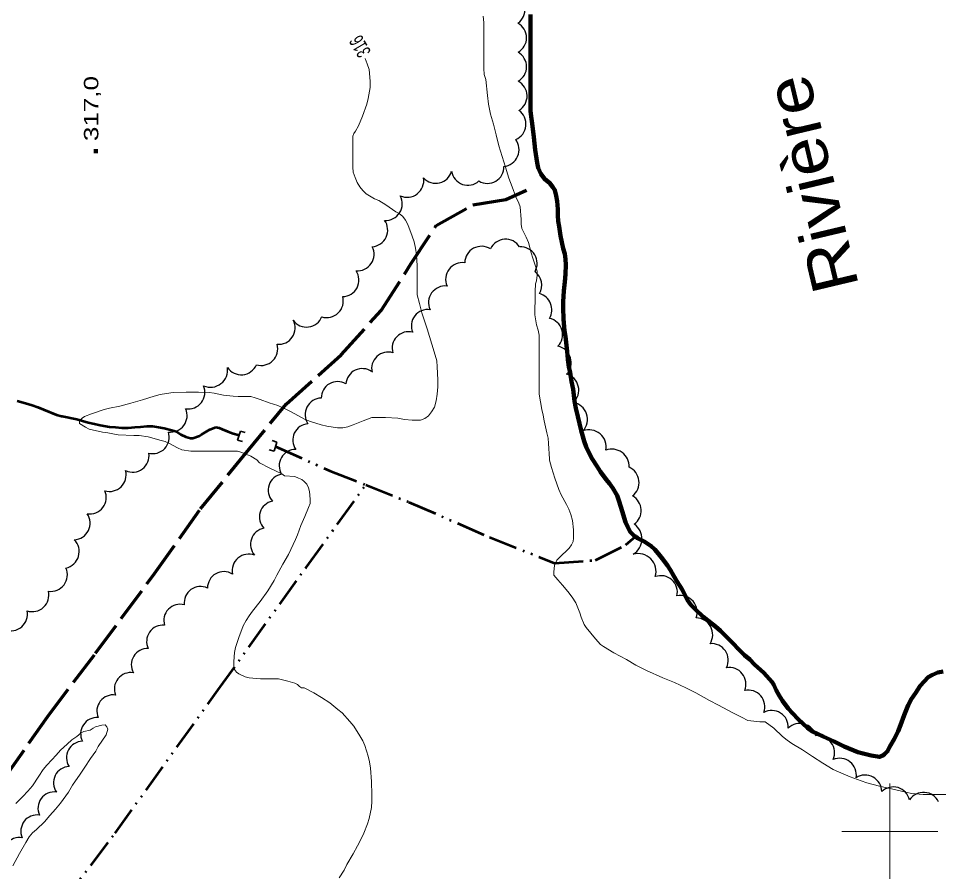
# Model space of a CAD drawing. Extents: x 240591 to 242335, y 5323482 to 5326937.
# Drawn here: x 242018.5 to 242210.1, y 5325991.6 to 5326169.4 of the extents above; entities that cross this region are included whole.
import ezdxf

# ---------------------------------------------------------------- set-up
doc = ezdxf.new("R2010")
doc.units = 0
doc.header["$LTSCALE"] = 1.2
doc.linetypes.add('DASH_DOUBLE_DOT', pattern=[9.2, 5, -1.2, 0.3, -1.2, 0.3, -1.2])
doc.linetypes.add('LONG_DASHED', pattern=[7.5, 6, -1.5])
for name, color, linetype, lineweight in [('2', 7, 'Continuous', 13), ('22', 7, 'LONG_DASHED', 70), ('26', 7, 'Continuous', 35), ('3', 7, 'Continuous', 140), ('4', 7, 'DASH_DOUBLE_DOT', 53), ('44', 7, 'Continuous', 25), ('61', 7, 'Continuous', 13)]:
    doc.layers.add(name, color=color, linetype=linetype, lineweight=lineweight)

msp = doc.modelspace()

# ---------------------------------------------------------------- linework, layer by layer
at = {"layer": '2'}
for points in [[(242126.5, 5326116.7), (242125.6, 5326119.4), (242125.3, 5326120.5), (242124.7, 5326122.7), (242124.2, 5326123.8), (242123.3, 5326125.6), (242123.2, 5326126.5), (242123.2, 5326127.5), (242123, 5326130.1), (242122.7, 5326130.9), (242122.1, 5326132.2), (242121.3, 5326134.3), (242120.6, 5326136.1), (242119.9, 5326138.4), (242119.2, 5326140.6), (242118.5, 5326142.8), (242118, 5326145.1), (242117.4, 5326147.3), (242116.8, 5326149.4), (242116.4, 5326151.5), (242116.2, 5326153.3), (242115.8, 5326156.6), (242115.5, 5326157.7), (242115.4, 5326158.9), (242115.4, 5326160.2), (242115.4, 5326162.9), (242115.4, 5326165.7), (242115.4, 5326168.5), (242115.3, 5326169.8)], [(242095, 5326130.5), (242093.5, 5326131.4), (242092.6, 5326131.8), (242090.9, 5326132.8), (242090.2, 5326133.5), (242089.6, 5326134.3), (242089, 5326135.2), (242088.6, 5326136.2), (242088.2, 5326137.3), (242088.1, 5326138.4), (242088.1, 5326139.4), (242088.1, 5326142.1), (242088.1, 5326144.8), (242088.3, 5326145.4), (242088.7, 5326145.9), (242089.3, 5326147), (242090.1, 5326149), (242091, 5326151.5), (242091.3, 5326152.7), (242091.7, 5326155), (242091.7, 5326156.3), (242091.5, 5326158.7), (242091.1, 5326159.9), (242090.7, 5326161)], [(242076, 5326073.9), (242073.9, 5326074.1), (242073.3, 5326074.5), (242070.8, 5326075.7), (242068.7, 5326076.8), (242068.1, 5326077.4), (242066.9, 5326078.2), (242066.4, 5326078.4), (242064.8, 5326079), (242064.1, 5326079.2), (242063.4, 5326079.2), (242060.3, 5326079.2), (242057.1, 5326079.2), (242054.4, 5326079.2), (242052.5, 5326079.5), (242051.6, 5326079.9), (242049.9, 5326080.8), (242049, 5326081.2), (242048.2, 5326081.4), (242045.5, 5326082.2), (242043.6, 5326082.5), (242042.5, 5326082.5), (242039.2, 5326082.6), (242038.1, 5326082.8), (242037.1, 5326083), (242036, 5326083.2), (242033.2, 5326083.8), (242032.4, 5326084.2), (242031.2, 5326085), (242031.2, 5326085.6), (242031.7, 5326086.1), (242032.2, 5326086.4), (242033.7, 5326087), (242036.3, 5326087.9), (242037.4, 5326088.2), (242039.6, 5326088.6), (242041.9, 5326089.2), (242044.3, 5326089.9), (242046.7, 5326090.7), (242048, 5326091), (242049.3, 5326091.2), (242050.7, 5326091.4), (242053.4, 5326091.5), (242056, 5326091.5), (242058.2, 5326091.4), (242059.2, 5326091.3), (242061.2, 5326090.9), (242063.2, 5326090.7), (242064.2, 5326090.6), (242066.9, 5326090.6), (242067.8, 5326090.3), (242068.8, 5326090), (242070.7, 5326089.3), (242072.5, 5326088.7), (242074.3, 5326087.9), (242075.3, 5326087.4), (242078.2, 5326085.8), (242079.3, 5326085.4), (242081.5, 5326084.7), (242082.7, 5326084.4), (242084.9, 5326084.1), (242086, 5326084.1), (242087.1, 5326084.3), (242088.2, 5326084.7), (242090.3, 5326085.5), (242092.1, 5326086.2), (242092.9, 5326086.2), (242094.9, 5326086.2), (242097.5, 5326086.1), (242098.9, 5326085.8), (242100.5, 5326085.7), (242102.2, 5326085.7), (242103.1, 5326086), (242103.9, 5326086.6), (242104.5, 5326087.4), (242105.1, 5326088.4), (242105.5, 5326089.7), (242105.7, 5326091.1), (242105.8, 5326092.6), (242105.8, 5326094.1), (242105.7, 5326096.8), (242105.6, 5326098), (242105.3, 5326099.2), (242104.6, 5326101.5), (242103.6, 5326104.7), (242102.5, 5326108), (242102, 5326110), (242101.5, 5326111.8), (242101.5, 5326112.8), (242101.5, 5326114.8), (242101.5, 5326117.8), (242101.4, 5326120.1), (242101.2, 5326121.5), (242100.9, 5326122.8), (242100.5, 5326124), (242099.6, 5326126.4), (242099.1, 5326127.3), (242098.5, 5326128.1), (242097.8, 5326128.7), (242097.1, 5326129.1), (242095, 5326130.5)], [(242172.9, 5326022.8), (242170.4, 5326023.1), (242169.1, 5326023.8), (242167.3, 5326024.7), (242164.3, 5326026.3), (242162.4, 5326027.3), (242159.6, 5326028.9), (242157.5, 5326029.9), (242155.1, 5326031), (242152.7, 5326032), (242149.3, 5326033.5), (242147.1, 5326034.6), (242145.1, 5326035.8), (242142.5, 5326037.2), (242140.3, 5326038.5), (242139.7, 5326038.9), (242138.7, 5326040.1), (242136.7, 5326042.5), (242136.3, 5326043.1), (242135.7, 5326044.6), (242135.4, 5326045.5), (242134.6, 5326047.6), (242133.8, 5326048.8), (242132.9, 5326050), (242131.8, 5326051.3), (242130.8, 5326052.4), (242130, 5326053.4), (242130, 5326054.1), (242130.1, 5326055.4), (242130.6, 5326056.5), (242131.1, 5326057), (242133.2, 5326059), (242133.7, 5326059.7), (242134, 5326060.4), (242134.1, 5326061.1), (242134.1, 5326062.8), (242133.9, 5326064.8), (242133.5, 5326066), (242133.1, 5326067.1), (242132.6, 5326068.1), (242131.5, 5326070.1), (242131, 5326071.2), (242130.2, 5326073.6), (242129.5, 5326075.8), (242129.1, 5326077.3), (242129.1, 5326077.6)], [(242212.2, 5326007.7), (242209.5, 5326007.7), (242206.9, 5326007.7), (242204.5, 5326007.9), (242203.3, 5326008.2), (242200.6, 5326008.8), (242197.8, 5326009.4), (242195.2, 5326010.1), (242194, 5326010.5), (242191.7, 5326011.4), (242189.3, 5326012.4), (242188.2, 5326012.9), (242186, 5326014.2), (242183.9, 5326015.6), (242181.8, 5326017), (242179.6, 5326018.3), (242178.6, 5326019), (242177.6, 5326019.8), (242175.8, 5326021.5), (242174, 5326022.8), (242173.4, 5326022.8), (242172.9, 5326022.8)], [(242033.4, 5326021.1), (242032.1, 5326020.8), (242031.5, 5326020.5), (242030.6, 5326019.8), (242029.6, 5326019.1), (242028.6, 5326018.2), (242027.2, 5326016.9), (242026.3, 5326015.9), (242025.4, 5326014.9), (242024.4, 5326013.8), (242023.6, 5326012.9), (242022.7, 5326011.5), (242021.4, 5326009.5), (242020.4, 5326008.4), (242019.4, 5326007.3), (242017.9, 5326005.8)]]:
    msp.add_lwpolyline(points, dxfattribs=at)
at = {"layer": '2', "linetype": 'LONG_DASHED'}
for points in [[(242129.1, 5326077.6), (242128.9, 5326080.8), (242128.8, 5326081.9), (242128.5, 5326083), (242128, 5326085.5), (242127.8, 5326086.7), (242127.5, 5326087.9), (242126.9, 5326091.1), (242126.9, 5326092.2), (242126.9, 5326095.8), (242126.9, 5326099.3), (242126.9, 5326102.4), (242126.9, 5326103.4), (242126.7, 5326104.4), (242126.4, 5326105.5), (242126, 5326107.6), (242126, 5326108.7), (242126.1, 5326110.7), (242126.1, 5326112.5), (242126.2, 5326114.1), (242126.4, 5326114.7), (242126.5, 5326115.9), (242126.5, 5326116.7)], [(242068.8, 5326047.9), (242070.4, 5326050.1), (242071.7, 5326052.3), (242072.3, 5326053.4), (242073.5, 5326055.7), (242074.7, 5326057.7), (242076.2, 5326060.8), (242076.6, 5326061.8), (242077.3, 5326063.7), (242078.1, 5326065.6), (242078.9, 5326067.5), (242079.2, 5326068.3), (242079.2, 5326069.2), (242079.1, 5326070.8), (242078.9, 5326071.6), (242078.5, 5326072.3), (242078, 5326072.9), (242077.5, 5326073.3), (242076.8, 5326073.6), (242076, 5326073.9)], [(242085.3, 5325990.3), (242086.3, 5325991.9), (242086.9, 5325993.1), (242088.2, 5325995.3), (242089.1, 5325997), (242090, 5325998.7), (242090.4, 5325999.6), (242091.2, 5326001.6), (242091.5, 5326002.7), (242092, 5326005), (242092.1, 5326006.3), (242092.1, 5326007.6), (242092, 5326010.4), (242091.8, 5326013.2), (242091.6, 5326014.5), (242091.3, 5326015.7), (242090.6, 5326017.9), (242090.2, 5326018.9), (242089.6, 5326019.9), (242088.3, 5326021.9), (242087.5, 5326022.9), (242085.9, 5326024.7), (242085, 5326025.4), (242083.3, 5326026.8), (242081.6, 5326027.9), (242080, 5326028.9), (242078, 5326029.9), (242077.4, 5326029.9), (242077, 5326030.2), (242076.6, 5326030.6), (242076, 5326030.9), (242074.6, 5326031.3), (242072.6, 5326031.8), (242071.7, 5326031.8), (242068.9, 5326031.8), (242066.5, 5326032), (242065.7, 5326032.2), (242064.4, 5326032.8), (242063.9, 5326033.2), (242063.5, 5326033.7), (242063.3, 5326034.5), (242063.3, 5326035.4), (242063.5, 5326037.3), (242063.7, 5326038.3), (242064.4, 5326040.4), (242065.3, 5326042.8), (242065.9, 5326043.9), (242066.5, 5326044.9), (242067.2, 5326045.9), (242068.8, 5326047.9)], [(242017.3, 5325992.8), (242018.7, 5325995.4), (242020, 5325997.7), (242020.7, 5325998.9), (242021.4, 5325999.7), (242022.2, 5326000.4), (242023.9, 5326002), (242025, 5326003.3), (242026.2, 5326004.6), (242027.2, 5326005.9), (242028.9, 5326008.2), (242029.7, 5326009.6), (242031.3, 5326011.9), (242032.3, 5326013.4), (242033.5, 5326015.2), (242034.6, 5326016.7), (242035.1, 5326017.7), (242036.7, 5326020.1), (242037.1, 5326021.3), (242036.9, 5326021.8), (242036.5, 5326022.2), (242035.8, 5326022.1), (242034.5, 5326021.8), (242034, 5326021.5), (242033.4, 5326021.1)]]:
    msp.add_lwpolyline(points, dxfattribs=at)
at = {"layer": '22'}
msp.add_lwpolyline([(241919.1, 5325890.8), (241928.3, 5325895.4), (241938.3, 5325902.7), (241946.8, 5325913.1), (241955.9, 5325924.8), (241965.6, 5325938.6), (241977, 5325954.3), (241986.1, 5325969.1), (241995.2, 5325983.1), (242004.1, 5325995.5), (242015.5, 5326011), (242024.5, 5326023.9), (242034.5, 5326037.1), (242046.8, 5326053.7), (242056.4, 5326067.2), (242065.2, 5326078), (242074.2, 5326089), (242085.7, 5326099.3), (242094, 5326108.5), (242100.2, 5326118.2), (242105.5, 5326126.2), (242113.1, 5326130.5), (242120, 5326131.6), (242124.3, 5326133.6)], dxfattribs=at)
at = {"layer": '26'}
for p, q in [((242064.1, 5326081.5), (242064.7, 5326083.4)), ((242064.7, 5326083.4), (242065.7, 5326083.1)), ((242064.1, 5326081.5), (242065.1, 5326081.2)), ((242072.3, 5326081.1), (242071.3, 5326081.4)), ((242071.7, 5326079.2), (242070.7, 5326079.5)), ((242072.3, 5326081.1), (242071.7, 5326079.2))]:
    msp.add_line(p, q, dxfattribs=at)
at = {"layer": '3'}
msp.add_line((242034.6, 5326141.3), (242034.6, 5326142.1), dxfattribs=at)
at = {"layer": '4', "linetype": 'Continuous', "lineweight": 90}
for points in [[(242125.1, 5326170.2), (242125.1, 5326167.5), (242125.1, 5326164.7), (242125.1, 5326161.5), (242125.1, 5326158.7), (242125.1, 5326155.5), (242125.1, 5326152.7), (242125.1, 5326150.1), (242125.3, 5326148.9), (242125.5, 5326147.5), (242125.8, 5326144.6), (242126.1, 5326142), (242126.5, 5326139.3), (242126.7, 5326138.2), (242127.3, 5326137), (242128.1, 5326135.9), (242129.1, 5326135.1), (242129.8, 5326134.2), (242130.2, 5326133.6), (242130.5, 5326132.4), (242130.7, 5326131.3), (242130.8, 5326129.6), (242130.8, 5326128.3), (242130.9, 5326127.1), (242131.1, 5326126), (242131.4, 5326124.1), (242131.9, 5326121.4), (242132.3, 5326120.3), (242132.4, 5326119.2), (242132.5, 5326118), (242132.4, 5326116.1), (242132.3, 5326114.5), (242132.1, 5326112.6), (242131.9, 5326110.3), (242131.9, 5326109.1), (242132, 5326106.7), (242132.2, 5326104.3), (242132.4, 5326103.1), (242132.8, 5326100), (242132.9, 5326098.3), (242133.1, 5326096.8), (242133.4, 5326095.6), (242133.7, 5326093.7), (242134, 5326092.1), (242134.3, 5326089.6), (242134.6, 5326088.2), (242135, 5326086.4), (242135.7, 5326083.5), (242136.3, 5326081.3), (242136.7, 5326080.1), (242137.2, 5326079.1), (242138, 5326077.6), (242139, 5326076), (242139.7, 5326074.9), (242140.9, 5326073.3), (242141.6, 5326072.5), (242142.3, 5326071.5), (242143.2, 5326070), (242143.6, 5326068.7), (242144.2, 5326066.7), (242144.9, 5326064.4), (242145.4, 5326063.4), (242145.9, 5326062.4), (242146.8, 5326061.5), (242147, 5326061.4)], [(242147, 5326061.4), (242147.4, 5326061.1), (242148.8, 5326060.4), (242150.2, 5326059.5), (242151, 5326058.7), (242151.8, 5326057.8), (242152.6, 5326056.8), (242153.7, 5326055.4), (242154.3, 5326054.4), (242154.9, 5326053.3), (242155.6, 5326052.1), (242156.7, 5326050.4), (242157.3, 5326049.3), (242157.8, 5326048.2), (242158.5, 5326047.2), (242159.4, 5326046.3), (242161.1, 5326044.7)], [(242161.1, 5326044.7), (242162.1, 5326043.9), (242163.7, 5326042.7), (242164.7, 5326041.8), (242165.6, 5326040.9), (242167.4, 5326039.1), (242168.3, 5326038.1), (242169.7, 5326036.7), (242170.8, 5326035.8), (242171.8, 5326034.8), (242173.7, 5326033), (242175.5, 5326031.1), (242175.8, 5326030.5), (242176.3, 5326029.4), (242176.9, 5326028.3), (242177.6, 5326027.2), (242178.8, 5326025.6), (242179.7, 5326024.6), (242180.9, 5326023.4), (242182.8, 5326021.6), (242183.9, 5326020.8), (242184.9, 5326020.3), (242186.1, 5326019.8), (242188.4, 5326018.7), (242190.5, 5326017.7), (242193.3, 5326016.5), (242194.4, 5326016.2), (242196.1, 5326015.8), (242197.8, 5326015.5), (242198.5, 5326015.8), (242198.9, 5326016.1), (242199.5, 5326016.7), (242200, 5326017.7), (242200.9, 5326019.2), (242201.7, 5326020.9), (242202.2, 5326022.1), (242203, 5326024.2), (242203.8, 5326026.3), (242204.5, 5326027.6), (242205.3, 5326028.8), (242206.3, 5326030.3), (242207.1, 5326031.2), (242208, 5326032.1), (242208.9, 5326032.6), (242210, 5326033.1), (242211.1, 5326033.3)]]:
    msp.add_lwpolyline(points, dxfattribs=at)
at = {"layer": '4'}
for points in [[(242018.2, 5326089.7), (242019.9, 5326089.2), (242021.3, 5326088.8), (242022.5, 5326088.4), (242023.7, 5326087.9), (242026.4, 5326086.8), (242027.4, 5326086.5), (242027.6, 5326086.5)], [(242027.6, 5326086.5), (242030.6, 5326085.9), (242031.8, 5326085.5), (242033, 5326085.2), (242034.3, 5326084.9), (242035.5, 5326084.6), (242037.4, 5326084.3), (242038.7, 5326084.2), (242040, 5326084.1), (242041.3, 5326084.1), (242042.7, 5326084.2), (242043.9, 5326084.3), (242045.2, 5326084.4), (242046.4, 5326084.4), (242047.6, 5326084.2), (242048.8, 5326084), (242050.4, 5326083.6), (242051.4, 5326083.3), (242052.3, 5326082.7), (242053.3, 5326082.2), (242054.3, 5326081.9), (242054.8, 5326081.9), (242056.2, 5326082.4), (242056.6, 5326082.7), (242058.3, 5326083.7), (242059.6, 5326084.2), (242060.3, 5326084.1), (242060.9, 5326083.8), (242062.1, 5326083.3), (242063.2, 5326082.9), (242064.2, 5326082.6), (242064.4, 5326082.4)], [(242072, 5326080.2), (242083.3, 5326075.1), (242090.8, 5326072.2)], [(241937, 5325854.4), (241947.3, 5325869.3), (241968.4, 5325901), (241993.4, 5325936), (242013.5, 5325966.5), (242038.6, 5325999.6), (242060, 5326029.4), (242078.4, 5326055), (242090.8, 5326072.2)], [(242090.8, 5326072.2), (242099.8, 5326068.6), (242116.6, 5326061.3), (242130.1, 5326055.9), (242138.7, 5326056.5), (242145, 5326059.7), (242147, 5326061.4)]]:
    msp.add_lwpolyline(points, dxfattribs=at)
at = {"layer": '44'}
for centre, radius, start, end in [((242126.078, 5326108.657), 3.494, 329.23586, 74.74436), ((242078.47, 5326108.498), 3.437, 215.75328, 339.06054), ((242128.346, 5326103.472), 3.477, 316.07852, 77.80789), ((242130.123, 5326097.655), 3.482, 316.30696, 77.94007), ((242064.865, 5326098.559), 3.437, 213.53655, 337.07502), ((242131.714, 5326091.902), 3.473, 312.70502, 74.5434), ((242133.429, 5326085.84), 3.568, 317.50929, 79.65071), ((242137.328, 5326080.095), 3.568, 348.67646, 110.81789), ((242142.095, 5326076.059), 3.568, 357.07916, 110.81789), ((242144.189, 5326072.646), 3.549, 308.53123, 65.55111), ((242144.722, 5326066.835), 3.468, 305.67875, 61.06311), ((242027.598, 5326058.291), 3.515, 282.52623, 44.61059), ((242025.197, 5326053.463), 3.458, 261.74549, 23.83309), ((242152.259, 5326049.806), 3.466, 347.23305, 109.18591), ((242021.352, 5326049.222), 3.446, 251.70155, 13.72797), ((242156.378, 5326045.636), 3.483, 340.44288, 102.23006), ((242016.863, 5326045.256), 3.477, 249.94182, 11.50649), ((242159.596, 5326040.984), 3.486, 327.2884, 88.9562), ((242029.163, 5326010.124), 3.4, 92.75222, 214.46283), ((242194.827, 5326008.249), 3.483, 0.66807, 122.41158), ((242200.713, 5326005.823), 3.444, 12.1818, 134.2558), ((242206.996, 5326004.666), 3.472, 25.12546, 147.13344), ((242022.349, 5326000.042), 3.394, 81.67502, 203.65859), ((242018.642, 5325995.343), 3.39, 79.83528, 202.06127)]:
    msp.add_arc(centre, radius, start, end, dxfattribs=at)
for centre, major_axis, ratio, start_param, end_param in [((242120.497, 5326171.188), (3.464, 0.072), 0.999503, 5.3118832, 7.4351143), ((242120.846, 5326165.332), (3.287, -1.096), 0.999962, 5.5451523, 7.6745969), ((242120.859, 5326159.29), (3.459, -0.139), 0.998126, 5.259769, 7.3868814), ((242120.945, 5326153.182), (3.471, -0.203), 0.999507, 5.3100113, 7.4357449), ((242120.701, 5326147.363), (3.426, -0.66), 0.999402, 5.3025735, 7.4239328), ((242119.183, 5326142.052), (3.172, -1.628), 0.998415, 5.3038801, 7.3882084), ((242105.398, 5326138.455), (0.58, -3.388), 0.998982, 5.2858519, 7.4062367), ((242112.088, 5326138.038), (-0.441, -3.413), 0.996141, 4.9944276, 7.1484397), ((242116.167, 5326138.431), (2.958, 1.749), 0.999862, 3.634958, 5.7775195), ((242099.397, 5326135.612), (2.147, -2.779), 0.999995, 5.216182, 7.3442143), ((242094.95, 5326130.74), (2.919, -1.872), 0.999995, 5.2189424, 7.3492351), ((242091.913, 5326125.258), (3.149, -1.462), 0.998035, 5.2174857, 7.3413749), ((242119.951, 5326119.874), (-2.861, -1.979), 0.999995, 3.1139807, 5.2451855), ((242089.072, 5326120.225), (2.796, -2.057), 0.99833, 5.264408, 7.3895869), ((242114.908, 5326118.409), (-1.802, -2.976), 0.999995, 3.1139807, 5.2451855), ((242123.036, 5326118.301), (-3.077, 1.623), 0.999995, 3.1139807, 5.2451855), ((242110.931, 5326115.007), (-0.404, -3.455), 0.999995, 3.1139805, 5.2451854), ((242085.958, 5326114.841), (-1.711, 2.976), 0.998151, 2.6313411, 4.7882732), ((242123.933, 5326113.782), (2.205, 2.757), 0.999995, 4.8670386, 6.3088325), ((242107.361, 5326110.15), (-2.834, 2.016), 0.997831, 5.2174671, 7.34271), ((242082.68, 5326110.481), (2.475, 2.401), 0.999615, 3.6390707, 5.7857072), ((242103.707, 5326105.314), (-2.437, 2.365), 0.999677, 5.3309729, 7.4608527), ((242072.656, 5326104.882), (3.308, -0.915), 0.995576, 4.8860876, 7.0440213), ((242099.707, 5326100.682), (-2.447, 2.369), 0.999724, 5.2192385, 7.3481275), ((242069.039, 5326100.502), (3.035, 1.606), 0.99974, 3.9277517, 6.0854885), ((242095.311, 5326096.538), (-1.994, -2.706), 0.964048, 3.4397845, 5.6020965), ((242058.438, 5326096.122), (2.201, -2.853), 0.999818, 5.2215684, 7.3470084), ((242090.002, 5326093.093), (-2.578, -2.164), 0.972636, 3.3759738, 5.5356812), ((242053.83, 5326091.461), (2.732, -2.129), 0.999978, 5.2179598, 7.3451661), ((242084.928, 5326090.298), (-1.486, 3.059), 0.999109, 5.2889931, 7.4103952), ((242081.644, 5326086.812), (0.188, -3.455), 0.999995, 3.120336, 5.2435114), ((242050.127, 5326086.634), (2.799, -2.055), 0.995718, 5.2173706, 7.336718), ((242046.435, 5326082.13), (1.493, -3.095), 0.996832, 5.5690192, 7.722378), ((242079.015, 5326081.514), (-3.103, 1.428), 0.992225, 5.2156069, 7.3273875), ((242076.176, 5326076.17), (-2.945, 1.701), 0.999796, 5.2200647, 7.3475941), ((242042.226, 5326078.264), (2.296, 2.553), 0.999673, 3.4392066, 5.5955309), ((242037.447, 5326074.27), (2.407, -2.475), 0.997799, 5.2173522, 7.3417278), ((242073.877, 5326071.08), (-2.693, 2.069), 0.99996, 5.5501765, 7.6746038), ((242033.275, 5326069.588), (2.694, -2.189), 0.996993, 5.2501496, 7.3772088), ((242072.054, 5326065.476), (-3.184, 1.19), 0.998632, 5.2752083, 7.3998327), ((242029.93, 5326064.21), (3.016, -1.691), 0.998677, 5.2720942, 7.3946487), ((242144.628, 5326060.946), (3.735, 0.113), 0.999925, 5.2162442, 7.225118), ((242070.202, 5326059.797), (-3.224, 1.097), 0.997496, 5.2203847, 7.3384558), ((242066.435, 5326054.291), (-2.243, 2.651), 0.999995, 5.2203613, 7.3491037), ((242147.535, 5326054.131), (2.652, 2.632), 0.999925, 5.2162442, 7.3444941), ((242061.241, 5326050.707), (-1.715, -2.948), 0.999995, 3.1162898, 5.2442759), ((242056.39, 5326047.605), (-2.003, 2.752), 0.999994, 5.2172571, 7.3440723), ((242052.143, 5326043.918), (-2.387, 2.429), 0.995708, 5.2462181, 7.3681103), ((242048.568, 5326039.565), (-2.752, 2.015), 0.996025, 5.2478151, 7.3688699), ((242162.862, 5326035.651), (2.859, 1.957), 0.999978, 5.2185014, 7.3495757), ((242045.366, 5326034.689), (-2.899, 1.776), 0.997727, 5.218742, 7.3414476), ((242041.852, 5326029.681), (-2.597, 2.211), 0.997135, 5.2548414, 7.375755), ((242166.526, 5326030.671), (2.814, 2.048), 0.998333, 5.2697461, 7.3891974), ((242170.447, 5326025.968), (2.633, 2.272), 0.998041, 5.2212314, 7.3448899), ((242038.193, 5326025.043), (-2.603, 2.188), 0.997841, 5.2604709, 7.3864098), ((242034.812, 5326020.322), (-2.512, 2.288), 0.999824, 5.374874, 7.4964092), ((242175.353, 5326021.721), (1.871, 2.932), 0.998041, 5.2212314, 7.3448899), ((242181.236, 5326019.024), (0.999, 3.331), 0.998041, 5.2689124, 7.3448899), ((242184.875, 5326016.359), (2.875, 2.182), 0.991248, 5.2322018, 7.2925208), ((242031.862, 5326015.365), (-2.908, 1.777), 0.998967, 5.2813869, 7.4046515), ((242189.522, 5326011.755), (-3.225, -1.319), 0.999984, 2.5904776, 4.7194434), ((242025.932, 5326004.823), (-2.739, 2.02), 0.999994, 5.2218229, 7.3500703)]:
    msp.add_ellipse(centre, major_axis=major_axis, ratio=ratio, start_param=start_param, end_param=end_param, dxfattribs=at)
at = {"layer": '61'}
for points in [[(242200, 5326010), (242200, 5326000), (242200, 5325990)], [(242190, 5326000), (242200, 5326000), (242210, 5326000)]]:
    msp.add_lwpolyline(points, dxfattribs=at)

# ---------------------------------------------------------------- texts
at = {"layer": '2', "width": 0.65}
msp.add_text('316', height=3, rotation=120.391, dxfattribs=at).set_placement((242092, 5326162.4))
at = {"layer": '3', "width": 1.35}
msp.add_text('317,0', height=3, rotation=90, dxfattribs=at).set_placement((242035.1, 5326143.8))
at = {"layer": '4', "width": 1.15}
msp.add_text('Rivière', height=9.6, rotation=103.378, dxfattribs=at).set_placement((242193.6, 5326113.6))

doc.saveas('drawing.dxf')
